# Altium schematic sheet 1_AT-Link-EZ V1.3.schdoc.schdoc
size 309 x 223 mm; Symbol: Artery_A4; Device: Artery_A4; Company: Artery Technology; Version: 1.0; Page Size: A4; @Project Name: AT-START-F423 V1.1; @Page Count: 4; @Update Date: 2024-03-29; @Create Date: 2023-04-24; @Schematic Name: AT-START-F423 V1.1; @Page No: 1; @Page Name: AT-Link-EZ V1.3
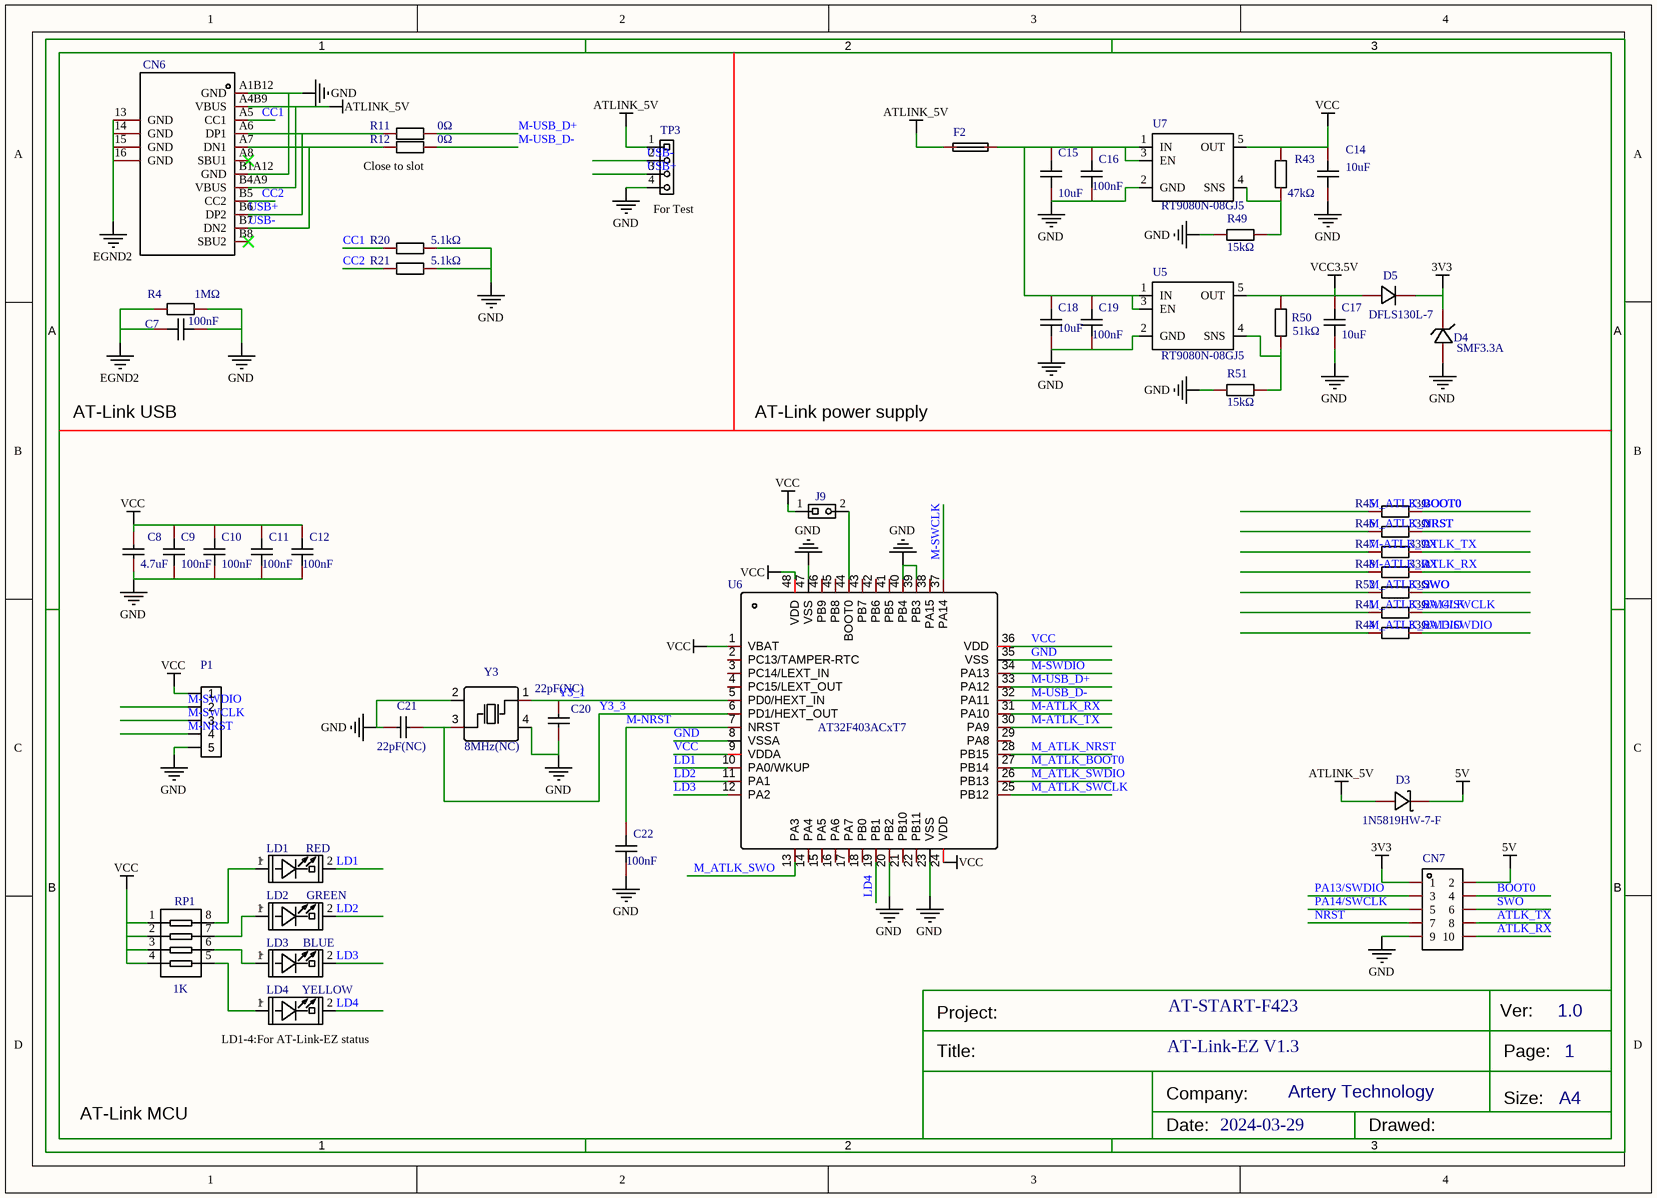
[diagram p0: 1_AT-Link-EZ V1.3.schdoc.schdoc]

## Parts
C7  value 100nF  [C0603]  (hidden comment: CC0603KRX7R9BB104)
C8  value 4.7uF  [C0603]  (hidden comment: CL10A475KO8NNNC)
C9  value 100nF  [C0603]  (hidden comment: CC0603KRX7R9BB104)
C10  value 100nF  [C0603]  (hidden comment: CC0603KRX7R9BB104)
C11  value 100nF  [C0603]  (hidden comment: CC0603KRX7R9BB104)
C12  value 100nF  [C0603]  (hidden comment: CC0603KRX7R9BB104)
C14  value 10uF  [C0603]  (hidden comment: CL10A106KP8NNNC)
C15  value 10uF  [C0603]  (hidden comment: CL10A106KP8NNNC)
C16  value 100nF  [C0603]  (hidden comment: CC0603KRX7R9BB104)
C17  value 10uF  [C0603]  (hidden comment: CL10A106KP8NNNC)
C18  value 10uF  [C0603]  (hidden comment: CL10A106KP8NNNC)
C19  value 100nF  [C0603]  (hidden comment: CC0603KRX7R9BB104)
C20  value 22pF(NC)  [C0603]  (hidden comment: CL10C220JB8NNNC)
C21  value 22pF(NC)  [C0603]  (hidden comment: CL10C220JB8NNNC)
C22  value 100nF  [C0603]  (hidden comment: CC0603KRX7R9BB104)
CN6  TYPEC-304-BCP16  [USB-C-SMD_TYPEC-304-BCP16]  (value not drawn)
CN7  Z-21310110021001  [HDR-TH_10P-P2.54-V-M-R2-C5-S2.54]  (value not drawn)
D3  1N5819HW-7-F  [SOD-123_L2.8-W1.8-LS3.7-FD]
D4  SMF3.3A  [SOD-123_L2.8-W1.8-LS3.7-RD]
D5  DFLS130L-7  [POWERDI-123_L2.8-W1.8-LS3.7-RD]
F2  SMD0603B050TF  [R0603]  (value not drawn)
J9  1X2P,Male,DIP_2.54  [HDR1X2]  (value not drawn)
LD1  RED  [LED0603]
LD2  GREEN  [LED0603]
LD3  BLUE  [LED0603]
LD4  YELLOW  [LED0603]
P1  HDR-M-2.54_1x5  [HDR-M-2.54_1X5]  (value not drawn)
R4  value 1MΩ  [R0603]  (hidden comment: RC0603FR-071ML)
R11  value 0Ω  [R0603]  (hidden comment: 0603WAF0000T5E)
R12  value 0Ω  [R0603]  (hidden comment: 0603WAF0000T5E)
R20  value 5.1kΩ  [R0603]  (hidden comment: 0603WAF5101T5E)
R21  value 5.1kΩ  [R0603]  (hidden comment: 0603WAF5101T5E)
R41  value 33Ω  [R0603]  (hidden comment: 0603WAF330JT5E)
R43  value 47kΩ  [R0603]  (hidden comment: 0603WAF4702T5E)
R44  value 33Ω  [R0603]  (hidden comment: 0603WAF330JT5E)
R45  value 33Ω  [R0603]  (hidden comment: 0603WAF330JT5E)
R46  value 33Ω  [R0603]  (hidden comment: 0603WAF330JT5E)
R47  value 33Ω  [R0603]  (hidden comment: 0603WAF330JT5E)
R48  value 33Ω  [R0603]  (hidden comment: 0603WAF330JT5E)
R49  value 15kΩ  [R0603]  (hidden comment: 0603WAF1502T5E)
R50  value 51kΩ  [R0603]  (hidden comment: 0603WAF5102T5E)
R51  value 15kΩ  [R0603]  (hidden comment: 0603WAF1502T5E)
R52  value 33Ω  [R0603]  (hidden comment: 0603WAF330JT5E)
RP1  1K  [0603*4,8P4R]
TP3  1X4P_2.54F  [HDR1X4 - TOP]  (value not drawn)
U5  RT9080N-08GJ5  [SOT-23-5]
U6  AT32F403ACxT7  [LQFP-48_L7.0-W7.0-P0.50-LS9.0-BL]
U7  RT9080N-08GJ5  [SOT-23-5(1)]
Y3  8MHz(NC)  [OSC-SMD_4P-L5.0-W3.2-BL]

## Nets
3V3: CN7.1 D4.1 D5.1
5V: CN7.2 D3.2(K)
ATLINK_5V: CN6.A4B9(VBUS) CN6.B4A9(VBUS) D3.1(A) F2.1 TP3.1
EGND2: C7.2 CN6.13(GND) CN6.14(GND) CN6.15(GND) CN6.16(GND) R4.1
GND: C7.1 C8.1 C9.1 C10.1 C11.1 C12.1 C14.1 C15.1 C16.1 C17.1 C18.1 C19.1 C20.1 C21.1 C22.1 CN6.A1B12(GND) CN6.B1A12(GND) CN7.9 D4.2 P1.5 R4.2 R20.2 R21.2 R49.1 R51.1 TP3.4 U5.2(GND) U6.8(VSSA) U6.20(PB2) U6.23(VSS) U6.35(VSS) U6.39(PB3) U6.40(PB4) U6.47(VSS) U7.2(GND) Y3.2(GND) Y3.4(GND)
VCC: C8.2 C9.2 C10.2 C11.2 C12.2 C14.2 J9.1 P1.1 R43.2 RP1.1 RP1.2 RP1.3 RP1.4 U6.1(VBAT) U6.9(VDDA) U6.24(VDD) U6.36(VDD) U6.48(VDD) U7.5(OUT)
VCC3.5V: C17.2 D5.2 R50.2 U5.5(OUT)
ATLK_RX: CN7.10 R48.2
ATLK_TX: CN7.8 R47.2
BOOT0: CN7.4 R45.2
CC1: CN6.A5(CC1) R20.1
CC2: CN6.B5(CC2) R21.1
LD1: LD1.2(CATHODE) U6.10(PA0/WKUP)
LD2: LD2.2(CATHODE) U6.11(PA1)
LD3: LD3.2(CATHODE) U6.12(PA2)
LD4: LD4.2(CATHODE) U6.19(PB1)
M-ATLK_RX: R48.1 U6.31(PA10)
M-ATLK_TX: R47.1 U6.30(PA9)
M-NRST: C22.2 P1.4 U6.7(NRST)
M-SWCLK: P1.3 U6.37(PA14)
M-SWDIO: P1.2 U6.34(PA13)
M-USB_D+: R11.2 U6.33(PA12)
M-USB_D-: R12.2 U6.32(PA11)
M_ATLK_BOOT0: R45.1 U6.27(PB14)
M_ATLK_NRST: R46.1 U6.28(PB15)
M_ATLK_SWCLK: R41.1 U6.25(PB12)
M_ATLK_SWDIO: R44.1 U6.26(PB13)
M_ATLK_SWO: R52.1 U6.13(PA3)
NRST: CN7.7 R46.2
PA13/SWDIO: CN7.3 R44.2
PA14/SWCLK: CN7.5 R41.2
SWO: CN7.6 R52.2
USB+: CN6.A6(DP1) CN6.B6(DP2) R11.1 TP3.3
USB-: CN6.A7(DN1) CN6.B7(DN2) R12.1 TP3.2
Y3_1: C20.2 U6.5(PD0/HEXT_IN) Y3.1(OSC1)
Y3_3: C21.2 U6.6(PD1/HEXT_OUT) Y3.3(OSC2)
NetC15_2: C15.2 C16.2 C18.2 C19.2 F2.2 U5.1(IN) U5.3(EN) U7.1(IN) U7.3(EN)
NetJ9_2: J9.2 U6.44(BOOT0)
NetLD1_1: LD1.1(ANODE) RP1.8
NetLD2_1: LD2.1(ANODE) RP1.7
NetLD3_1: LD3.1(ANODE) RP1.6
NetLD4_1: LD4.1(ANODE) RP1.5
NetR43_1: R43.1 R49.2 U7.4(SNS)
NetR50_1: R50.1 R51.2 U5.4(SNS)

Not connected (* = marked no-connect by the designer): CN6 A8(SBU1)* B8(SBU2)*; U6 2(PC13/TAMPER-RTC) 3(PC14/LEXT_IN) 4(PC15/LEXT_OUT) 14(PA4) 15(PA5) 16(PA6) 17(PA7) 18(PB0) 21(PB10) 22(PB11) 29(PA8) 38(PA15) 41(PB5) 42(PB6) 43(PB7) 45(PB8) 46(PB9)

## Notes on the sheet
- (near R12) Close to slot
- (near TP3) For Test
- AT-Link USB
- AT-Link power supply
- AT-START-F423
- (near LD4) LD1-4:For AT-Link-EZ status
- AT-Link-EZ V1.3
- AT-Link MCU
- 2024-03-29

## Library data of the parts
C7 C9-C12 C16 C19 C22 = CC0603KRX7R9BB104: Manufacturer: YAGEO(国巨); Add into BOM: yes; Tolerance: ±10%; Voltage Rated: 50V; Temperature Coefficient: X7R; Description: 容值:100nF;精度:±10%;额定电压:50V;温度系数:X7R;
C8 = CL10A475KO8NNNC: Manufacturer: SAMSUNG(三星); Add into BOM: yes; Tolerance: ±10%; Voltage Rated: 16V; Temperature Coefficient: X5R; Description: 容值:4.7uF;精度:±10%;额定电压:16V;温度系数:X5R;
C14 C15 C17 C18 = CL10A106KP8NNNC: Manufacturer: SAMSUNG(三星); Add into BOM: yes; Tolerance: ±10%; Voltage Rated: 10V; Temperature Coefficient: X5R; Description: 容值:10uF;精度:±10%;额定电压:10V;温度系数:X5R;
C20 C21 = CL10C220JB8NNNC: Manufacturer: SAMSUNG(三星); Add into BOM: yes; Tolerance: ±5%; Voltage Rated: 50V; Temperature Coefficient: C0G; Description: 容值:22pF;精度:±5%;额定电压:50V;温度系数:C0G;
CN6 = TYPEC-304-BCP16: 连接器类型:Type-C;标准:USB 3.1;公母:母座;触点数量:16.0;端口数量:1;安装方式:卧贴;额定电流 - 电源:3A;工作温度范围:-25~+85;焊接温度(最大值):260;; Manufacturer: XUNPU(讯普); Add into BOM: yes; Connector Type: Type-C; Gender: 母座; Number of Contacts: 16.0; Number of Ports: 1; Mounting Sytle: 卧贴; Current Rating - Power (Max): 3A; Welding Temperature (Max): 260
CN7 = Z-21310110021001: Manufacturer: Nextron(台湾正凌); Add into BOM: yes; Pitch: 2.54mm; Description: 间距:2.54mm;总PIN位数:10;排数:2;插针结构:-;行距:2.54mm;安装类型:直插;圆针/方针:-;额定电流:-;额定电压:-;配合针长度:-;塑高:-;触头材质:黄铜;触头镀层:-;颜色:黑色;
D3 = 1N5819HW-7-F: Manufacturer: DIODES(美台); Add into BOM: yes; Reverse Voltage (Vr): 40V; Average Rectified Current (Io): 1A; Forward Voltage (Vf@If): 450mV@1A; Description: 直流反向耐压(Vr):40V;平均整流电流(Io):1A;正向压降(Vf):450mV@1A;
D4 = SMF3.3A: Manufacturer: DOWO; Paste Type: expand; Convert to PCB: yes
D5 = DFLS130L-7_POWERDI-123_L2.8-W1.8-LS3.7-RD: Manufacturer: Diodes Incorporated; Paste Type: expand; Convert to PCB: yes
F2 = SMD0603B050TF: Manufacturer: Brightking Elec (TAIWAN); Manufacturer Part: SMD0603B035TF; Paste Type: expand; Convert to PCB: yes
J9 = 1X2P,Male,DIP_2.54: Convert to PCB: yes
LD1 = RED: Convert to PCB: yes
LD2 = GREEN: Convert to PCB: yes
LD3 = BLUE: Convert to PCB: yes
LD4 = YELLOW: Convert to PCB: yes
P1 = HDR-M-2.54_1x5: Convert to PCB: yes
R4 = RC0603FR-071ML: 阻值:1MΩ;精度:±1%;功率:100mW;温度系数:±100ppm/;最大工作电压:75V;工作温度范围:-55~+155;; Manufacturer: YAGEO(国巨); Add into BOM: yes; Tolerance: ±1%; Power(Watts): 100mW; Overload Voltage (Max): 75V
R11 R12 = 0603WAF0000T5E: 电阻类型:厚膜电阻;阻值:0Ω;精度:±1%;功率:1/10W;温度系数:-;最大工作电压:75V;工作温度范围:-55~+155;; Manufacturer: UNI-ROYAL(厚声); Add into BOM: yes; Tolerance: ±1%; Power(Watts): 1/10W; Overload Voltage (Max): 75V
R20 R21 = 0603WAF5101T5E: 电阻类型:厚膜电阻;阻值:5.1kΩ;精度:±1%;功率:1/10W;温度系数:±100ppm/;最大工作电压:75V;工作温度范围:-55~+155;; Manufacturer: UNI-ROYAL(厚声); Add into BOM: yes; Tolerance: ±1%; Power(Watts): 1/10W; Overload Voltage (Max): 75V
R41 R44-R48 R52 = 0603WAF330JT5E: 电阻类型:厚膜电阻;阻值:33Ω;精度:±1%;功率:1/10W;温度系数:±100ppm/;最大工作电压:75V;工作温度范围:-55~+155;; Manufacturer: UNI-ROYAL(厚声); Add into BOM: yes; Tolerance: ±1%; Power(Watts): 1/10W; Overload Voltage (Max): 75V
R43 = 0603WAF4702T5E: 电阻类型:厚膜电阻;阻值:47kΩ;精度:±1%;功率:1/10W;温度系数:±100ppm/;最大工作电压:75V;工作温度范围:-55~+155;; Manufacturer: UNI-ROYAL(厚声); Add into BOM: yes; Tolerance: ±1%; Power(Watts): 1/10W; Overload Voltage (Max): 75V
R49 R51 = 0603WAF1502T5E: 电阻类型:厚膜电阻;阻值:15kΩ;精度:±1%;功率:1/10W;温度系数:±100ppm/;最大工作电压:75V;工作温度范围:-55~+155;; Manufacturer: UNI-ROYAL(厚声); Add into BOM: yes; Tolerance: ±1%; Power(Watts): 1/10W; Overload Voltage (Max): 75V
R50 = 0603WAF5102T5E: 电阻类型:厚膜电阻;阻值:51kΩ;精度:±1%;功率:1/10W;温度系数:±100ppm/;最大工作电压:75V;工作温度范围:-55~+155;; Manufacturer: UNI-ROYAL(厚声); Add into BOM: yes; Tolerance: ±1%; Power(Watts): 1/10W; Overload Voltage (Max): 75V
RP1 = 1K: Convert to PCB: yes
TP3 = 1X4P_2.54F: Convert to PCB: yes
U5 = RT9080N-08GJ5: Convert to PCB: yes
U6 = AT32F403ACxT7: Manufacturer: Artery Technology; Add into BOM: yes; Description: 由官方提供
U7 = RT9080N-08GJ5_SOT-23-5: Convert to PCB: yes
Y3 = 8MHz: Manufacturer: TAE; Manufacturer Part: SMD-5032_4P8M20pf20ppm; Paste Type: recommend; Convert to PCB: yes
